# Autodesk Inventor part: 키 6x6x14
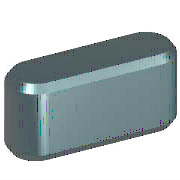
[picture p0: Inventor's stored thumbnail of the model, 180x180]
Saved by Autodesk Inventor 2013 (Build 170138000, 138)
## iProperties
IsCustomPart: 1
Created: 2012-02
Part Number: 키 6x6x14
Material: 강철, 연강
Description: 평행 키
Document SubType Name: Modeling
Standard: JIS B 1301
Designer: mdu-01
Standards Organization: JIS
Language: ko-KR
Size Designation: 6x6x14
Categories: <MemberInstance><Categories><Category DisplayName="샤프트 부품" InternalName="7f7aeb1f-a693-4053-b835-cee3144e0d98" Mnemonic="SHFT"><Category DisplayName="키" Interna
Density: 1 g/cm^3
Author: mdu-01
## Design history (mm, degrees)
workplane "Work Plane1"
workplane "Work Plane2"
sketch "스케치1"
  geometry: L1 (3, 3)-(11, 3); L2 (11, -3)-(3, -3); L3 (0, 9.4)-(0, -7.4) reference; L4 (-5, 0)-(30, 0) reference; L5 (14, 0)-(14, 7); A1 r 3 centre (3, 0) between (3, 3) and (3, -3); A2 r 3 centre (11, 0) between (11, -3) and (11, 3)
  constraints: 6 end point, 5 point on circle, 4 tangent, 3 point on line, 2 centre point, 1 horizontal, 1 parallel, 1 perpendicular
  dimensions: "d0" = 3 radius of A1 (= 0.5 x PB); "d13" = 3 radius of A2 (= 0.5 x PB); "d14" = 14 distance between parallel lines of L5 L3 (= NLG)
extrude "본체1" new body sketch "스케치1" taper "d3" = 0 deg; stored distance "d4" = 10
workplane "Work Plane3"
body "Solid1"
chamfer "모따기1" distance "d8" = 0.4 (= PHH); stored, may be unused: second distance "d9" = 0.4 (= PHH), angle "d15" = 45 deg
other parameters: "d1" = -3.5 (= -PNT), "d2" = 2.5 (= PH - PNT), "NLG" = 14 [user parameter; used in 3 equation terms], "PB" = 6 [user parameter; used in 2 equation terms], "PNT" = 3.5 [user parameter; used in 2 equation terms], "PH" = 6 [user parameter; used in 1 equation term], "PHH" = 0.4 [user parameter; used in 2 equation terms], "d10" = 0, "d16" = 0, "d17" = 0, "d18" = 0, "WDMIN" = 17 [user parameter], "PLB2" = 14 (= NLG) [user parameter], "WDMAX" = 22 [user parameter], "PLB1" = 14 (= NLG) [user parameter], "RR" = 0.16 [user parameter], "PUEB" = 2.8 [user parameter]
